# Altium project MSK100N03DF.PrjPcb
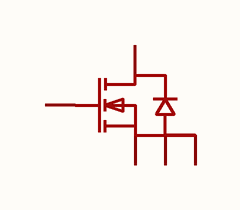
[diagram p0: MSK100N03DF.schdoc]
1 sheet, 1 parts. Net scope: global (net labels, ports and power ports of the same name join across sheets).

## Sheet MSK100N03DF.schdoc
size 127 x 101 mm

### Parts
Q?  msk100n03df  [DFN-8_L3.3-W3.3-P0.65-BL-2]  (value not drawn)

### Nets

Not connected (* = marked no-connect by the designer): Q? 1(S) 2(S) 3(S) 4(G) 5(D)

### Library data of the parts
Q? = msk100n03df: 数量:1个N沟道;漏源电压(Vdss):30V;连续漏极电流(Id):100A;导通电阻(RDS(on)):4mΩ@10V;耗散功率(Pd):62.5W;阈值电压(Vgs(th)):2.5V;; Manufacturer: MSKSEMI(美森科); AddInBom: yes; ModelId: 720567037d40416ca2f14c632ba061bb; ModelTransform: 129.921,130.708,0,0,0,0,0.196,33.275,0; Number: 1个N沟道; Drain to Source Voltage: 30V; Current - Continuous Drain(Id): 100A; Pd - Power Dissipation: 62.5W; Gate Threshold Voltage (Vgs(th)): 2.5V; Gate Charge(Qg): 31.6nC; Input Capacitance(Ciss): 3.075nF; Reverse Transfer Capacitance (Crss@Vds): 315pF; Type: N沟道; Output Capacitance(Coss): 400pF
